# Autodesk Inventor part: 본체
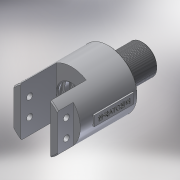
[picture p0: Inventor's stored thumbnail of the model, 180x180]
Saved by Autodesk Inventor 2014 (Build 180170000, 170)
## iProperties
Created: 2019-02
Part Number: 본체
Material: 알루미늄 6061
Document SubType Name: Modeling
Designer: 703-04
Density: 2.71 g/cm^3
Appearance: 알루미늄 - 평지
Author: 703-04
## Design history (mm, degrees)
sketch "스케치1"
  geometry: L1 (-54, 0)-(54, 0); L2 (-54, 0)-(-54, 29); L3 (-54, 29)-(20, 29); L4 (20, 29)-(20, 13); L5 (20, 13)-(25, 13); L6 (25, 13)-(25, 15); L7 (25, 15)-(54, 15); L8 (54, 15)-(54, 0); L9 (-18, 0)-(-18, 14); L10 (-18, 14)-(-15.35, 14); L11 (-15.35, 14)-(-15.35, 17); L12 (-15.35, 17)-(-10.65, 17); L13 (-10.65, 17)-(-10.65, 14); L14 (-10.65, 14)-(-6.35, 14); L15 (-6.35, 14)-(-6.35, 17); L16 (-6.35, 17)-(-1.65, 17); L17 (-1.65, 17)-(-1.65, 14); L18 (-1.65, 14)-(2, 14); L19 (2, 14)-(2, 16); L20 (2, 16)-(9, 16); L21 (9, 16)-(9, 0); L22 (-13, 17)-(-13, 0); L23 (-4, 17)-(-4, 0); 2 further points
  constraints: 46 end point, 15 parallel, 5 perpendicular, 4 point on line, 3 midpoint, 2 collinear, 1 coincident, 1 horizontal
  dimensions: "d0" = 108 distance of L1.start L1.end; "d1" = 58 diameter of L3 L1; "d2" = 74 distance of L2.end L3.end; "d3" = 5 distance of L4.end L5.end; "d4" = 30 diameter of L7 L1; "d5" = 26 diameter of L5 L1; "d6" = 36 distance between parallel lines of L2 L9; "d7" = 5 distance between parallel lines of L9 L22; "d8" = 4.7 distance of L11.end L12.end; "d9" = 4.7 distance of L15.end L16.end; "d10" = 7 distance of L19.end L20.end; "d11" = 9 distance between parallel lines of L23 L22; "d12" = 20 distance between parallel lines of L9 L19; "d13" = 28 diameter of L10 L1; "d14" = 28 diameter of L14 L1 (= d13); "d15" = 28 diameter of L18 L1 (= d14); "d16" = 34 diameter of L12 L1; "d17" = 34 diameter of L16 L1 (= d16); "d48" = 32 diameter of L20 L1
revolve "회전1" sketch "스케치1" stored, may be unused: angle "d19" = 90 deg
sketch "스케치2"
  geometry: L1 (54, 29)-(54, -29) reference; L2 (54, -29)-(-20, -29) reference; L3 (-20, -29)-(-20, -13) reference; L4 (-20, -13)-(-25, -13) reference; L5 (-25, -13)-(-25, -15) reference; L6 (-25, -15)-(-54, -15) reference; L7 (-54, -15)-(-54, 15) reference; L8 (-54, 15)-(-25, 15) reference; L9 (-25, 15)-(-25, 13) reference; L10 (-25, 13)-(-20, 13) reference; L11 (-20, 13)-(-20, 29) reference; L12 (-20, 29)-(54, 29) reference; L13 (18, -14)-(18, 14) reference; L14 (18, 14)-(15.35, 14) reference; L15 (15.35, 14)-(15.35, 17) reference; L16 (15.35, 17)-(10.65, 17) reference; L17 (10.65, 17)-(10.65, 14) reference; L18 (10.65, 14)-(6.35, 14) reference; L19 (6.35, 14)-(6.35, 17) reference; L20 (6.35, 17)-(1.65, 17) reference; L21 (1.65, 17)-(1.65, 14) reference; L22 (1.65, 14)-(-2, 14) reference; L23 (-2, 14)-(-2, 16) reference; L24 (-2, 16)-(-9, 16) reference; L25 (-9, 16)-(-9, -16) reference; L26 (-9, -16)-(-2, -16) reference; L27 (-2, -16)-(-2, -14) reference; L28 (-2, -14)-(1.65, -14) reference; L29 (1.65, -14)-(1.65, -17) reference; L30 (1.65, -17)-(6.35, -17) reference; L31 (6.35, -17)-(6.35, -14) reference; L32 (6.35, -14)-(10.65, -14) reference; L33 (10.65, -14)-(10.65, -17) reference; L34 (10.65, -17)-(15.35, -17) reference; L35 (15.35, -17)-(15.35, -14) reference; L36 (15.35, -14)-(18, -14) reference; L37 (54, -15)-(18, -15); L38 (18, -15)-(18, 15); L39 (18, 15)-(54, 15); L40 (54, 15)-(54, -15); 1 further point
  constraints: 8 end point, 2 parallel, 2 point on line, 1 horizontal, 1 perpendicular
  dimensions: "d20" = 15 distance from line of L37 point (0, 0); "d21" = 30 distance between parallel lines of L39 L37
extrude "돌출1" cut sketch "스케치2" stored distance "d22" = 114.25; taper "d23" = 0 deg
sketch "스케치3"
  geometry: L1 (54, -29)-(-20, -29) reference; L2 (-20, -29)-(-20, -13) reference; L3 (-20, -13)-(-25, -13) reference; L4 (-25, -13)-(-25, -15) reference; L5 (-25, -15)-(-54, -15) reference; L6 (-54, -15)-(-54, 15) reference; L7 (-54, 15)-(-25, 15) reference; L8 (-25, 15)-(-25, 13) reference; L9 (-25, 13)-(-20, 13) reference; L10 (-20, 13)-(-20, 29) reference; L11 (-20, 29)-(54, 29) reference; L12 (54, 29)-(54, 15) reference; L13 (54, 15)-(18, 15) reference; L14 (18, 15)-(18, 14) reference; L15 (18, 14)-(15.35, 14) reference; L16 (15.35, 14)-(15.35, 17) reference; L17 (15.35, 17)-(10.65, 17) reference; L18 (10.65, 17)-(10.65, 14) reference; L19 (10.65, 14)-(6.35, 14) reference; L20 (6.35, 14)-(6.35, 17) reference; L21 (6.35, 17)-(1.65, 17) reference; L22 (1.65, 17)-(1.65, 14) reference; L23 (1.65, 14)-(-2, 14) reference; L24 (-2, 14)-(-2, 16) reference; L25 (-2, 16)-(-9, 16) reference; L26 (-9, 16)-(-9, -16) reference; L27 (-9, -16)-(-2, -16) reference; L28 (-2, -16)-(-2, -14) reference; L29 (-2, -14)-(1.65, -14) reference; L30 (1.65, -14)-(1.65, -17) reference; L31 (1.65, -17)-(6.35, -17) reference; L32 (6.35, -17)-(6.35, -14) reference; L33 (6.35, -14)-(10.65, -14) reference; L34 (10.65, -14)-(10.65, -17) reference; L35 (10.65, -17)-(15.35, -17) reference; L36 (15.35, -17)-(15.35, -14) reference; L37 (15.35, -14)-(18, -14) reference; L38 (18, -14)-(18, -15) reference; L39 (18, -15)-(54, -15) reference; L40 (54, -15)-(54, -29) reference; L41 (54, -22)-(38, -22); L42 (38, -22)-(38, -30.899); L43 (38, -30.899)-(54, -30.899); L44 (54, -30.899)-(54, -22); L45 (0, 0)-(47.459, 0); L46 (38, 30.899)-(54, 30.899); L47 (38, 22)-(38, 30.899); L48 (54, 22)-(38, 22); L49 (54, 30.899)-(54, 22)
  constraints: 18 end point, 4 symmetric about line, 2 parallel, 2 perpendicular, 1 horizontal, 1 midpoint
  dimensions: "d24" = 22 distance from line of L45.start L41; "d25" = 16 distance of L42.end L43.end
extrude "돌출2" cut sketch "스케치3" stored distance "d26" = 114.25; taper "d27" = 0 deg
sketch "스케치4"
  geometry: L1 (0, 0)-(0, 37.789) reference; 3 further points
  dimensions: "d28" = 9 distance from line of point (9, 9.894) L1; "d29" = 9 distance from line of L1 point (9, 27.894); "d30" = 9 vertical distance of point (54, 18.894) point (9, 27.894); "d31" = 18 distance of point (9, 9.894) point (9, 27.894)
hole "구멍1" sketch "스케치4" at (9, 27.894), (9, 9.894) diameter "d32" = 6; stored, may be unused: countersink angle "d36" = 90 deg, drill point angle "d38" = 118 deg; dims "d33" = 6, "d34" = 4, "d35" = 2, "d37" = 8
hole "구멍2" diameter "d41" = 12.376; stored, may be unused: countersink angle "d45" = 90 deg, drill point angle "d47" = 120 deg; dims "d39" = 10, "d40" = 10, "d42" = 18, "d43" = 4, "d44" = 2, "d46" = 22
sketch "스케치5"
  geometry: C1 r 4 at (0, 0); 1 further point
  constraints: 1 centre point, 1 coincident
  dimensions: "d49" = 8 diameter of C1
extrude "돌출3" cut sketch "스케치5" distance "d50" = 114.25; taper "d51" = 0 deg
chamfer "모따기1" distance "d52" = 1; stored, may be unused: second distance "d53" = 2, angle "d54" = 45 deg
chamfer "모따기2" distance "d55" = 1; stored, may be unused: second distance "d56" = 2, angle "d57" = 45 deg
feature "스레드1" dims "d58" = 10, "d59" = 0
chamfer "모따기3" distance "d60" = 1; stored, may be unused: second distance "d61" = 2, angle "d62" = 45 deg
node "작업 평면1"
sketch "스케치6"
  geometry: L1 (-25, 5)-(15, 5); L2 (15, 5)-(15, -5); L3 (15, -5)-(-25, -5); L4 (-25, -5)-(-25, 5); L5 (20, 28)-(20, -28) reference; 1 further point
  constraints: 8 end point, 2 parallel, 1 horizontal, 1 perpendicular
  dimensions: "d64" = 5 distance from line of L1 point (0, 0); "d65" = 10 distance between parallel lines of L3 L1; "d66" = 5 distance between parallel lines of L5 L2; "d67" = 40 distance of L1.start L1.end
extrude "돌출4" join sketch "스케치6" stored distance "d68" = 114.25; taper "d69" = 0 deg
sketch "스케치7"
  geometry: L1 (-25, 5)-(15, 5) reference; L2 (-25, -5)-(-25, 5) reference; L3 (15, -5)-(-25, -5) reference; L4 (15, 5)-(15, -5) reference; 2 further points
  constraints: 1 other
  dimensions: "d70" = 20 distance from line of point (-5, 0) L2; "d71" = 5 distance from line of point (-5, 0) L3
feature "엠보싱1" sketch "스케치7" dims "d0" = 108, "d1" = 58, "d2" = 74, "d3" = 5, "d4" = 30, "d5" = 26, "d6" = 36, "d7" = 5, "d8" = 4.7, "d9" = 4.7, "d10" = 7, "d11" = 9, "d12" = 20, "d13" = 28, "d14" = 28 (= d13), "d15" = 28 (= d14), "d16" = 34, "d17" = 34 (= d16), "d48" = 32, "d72" = 0.5, "d73" = 0
fillet "모깎기1" dims "d74" = 0.8
node "솔리드1"
node "투영된 루프1"
node "절단 모서리 투영1"
node "절단 모서리 투영2"
